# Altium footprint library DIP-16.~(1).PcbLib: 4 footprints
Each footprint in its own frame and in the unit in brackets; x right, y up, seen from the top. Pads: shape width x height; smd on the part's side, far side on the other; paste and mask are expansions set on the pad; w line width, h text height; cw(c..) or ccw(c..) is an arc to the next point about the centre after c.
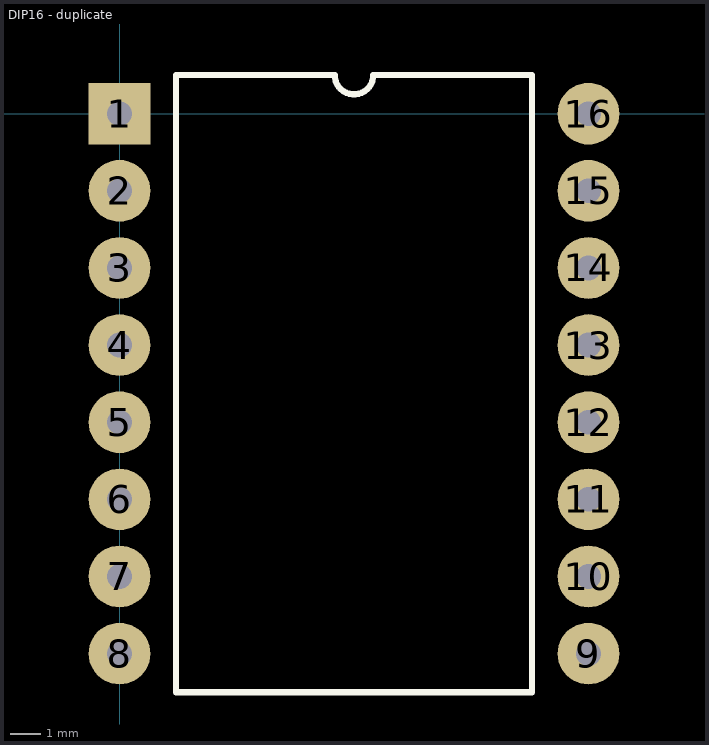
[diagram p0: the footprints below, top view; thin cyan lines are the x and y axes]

## DIP16 [mm]

## DIP16 - duplicate [mm]
pads (16):
  rect 2x2 hole 0.8: 1(0,0)
  round 2 hole 0.8: 2(0,-2.5) 3(0,-5) 4(0,-7.5) 5(0,-10) 6(0,-12.5) 7(0,-15) 8(0,-17.5) 9(15.2,-17.5) 10(15.2,-15) 11(15.2,-12.5) 12(15.2,-10) 13(15.2,-7.5) 14(15.2,-5) 15(15.2,-2.5) 16(15.2,0)
Top Overlay:
  lines w0.2: 1.835,-18.75 1.835,1.25 6.975,1.25 ccw(c7.6,1.25) 8.225,1.25 13.365,1.25 13.365,-18.75 1.835,-18.75

## PCBComponent_1 [mm]

## PCBComponent_1 - duplicate [mm]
